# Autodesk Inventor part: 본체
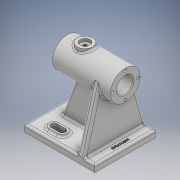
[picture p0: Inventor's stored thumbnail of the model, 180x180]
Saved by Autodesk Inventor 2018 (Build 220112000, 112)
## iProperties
Created: 2019-10
Part Number: 본체
Material: Generic
Document SubType Name: Sheet Metal
Designer: Administrator
Density: 1 g/cm^3
Appearance: Default
Sheet Metal Rule: 기본값
Author: Administrator
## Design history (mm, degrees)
sketch "스케치6"
  geometry: L1 (50, -43)-(-50, -43); L2 (-50, -43)-(-50, 43); L3 (-50, 43)-(50, 43); L4 (50, 43)-(50, -43); L5 (50, -43)-(-50, 43); L6 (-50, -43)-(50, 43); 1 further point
  constraints: 12 end point, 2 midpoint, 2 parallel, 1 horizontal, 1 perpendicular
  dimensions: "d2" = 100 distance of L2.end L3.end; "d3" = 86 distance of L3.end L1.start
extrude "돌출1" new body sketch "스케치6" distance "d4" = 10; taper "d5" = 0 deg
sketch "스케치7"
  geometry: L1 (-50, 0)-(50, 0) reference; L2 (-50, 0)-(-50, 10) reference; L3 (50, 10)-(-50, 10) reference; L4 (50, 0)-(50, 10) reference; L5 (-50, 86)-(32, 86); L6 (-50, 107)-(32, 107); L7 (32, 107)-(32, 86); L8 (-50, 107)-(-50, 86); 1 further point
  constraints: 8 end point, 1 parallel, 1 perpendicular, 1 vertical
  dimensions: "d6" = 86 distance of L1.start L5.start; "d7" = 82 distance of L5.start L5.end; "d8" = 21 distance between parallel lines of L5 L6
revolve "회전1" sketch "스케치7" stored, may be unused: angle "d9" = 90 deg
sketch "스케치8"
  geometry: L1 (50, 0)-(-50, 0) reference; L2 (50, 0)-(50, 10) reference; L3 (-50, 10)-(50, 10) reference; L4 (-50, 0)-(-50, 10) reference; L5 (-50, 65)-(-50, 107) reference; L6 (32, 65)-(32, 107) reference; L7 (-50, 65)-(32, 65) reference; L8 (50, 0)-(50, 10) reference; L9 (-50, 10)-(50, 10) reference; L10 (35, 10)-(13.162, 70); L11 (-25, 70)-(13.162, 70); L12 (35, 10)-(-25, 10); L13 (-25, 10)-(-25, 70); L14 (35, 10)-(-25, 10); 1 further point
  constraints: 10 end point, 2 point on line, 1 collinear, 1 perpendicular
  dimensions: "d12" = 70 deg angle of L3 L10
extrude "돌출2" join sketch "스케치8" stored distance "d14" = 10; taper "d15" = 0 deg
sketch "스케치9"
  geometry: L1 (76, 5)-(20.396, 5) reference; L2 (76, -5)-(76, 5) reference; L3 (20.396, -5)-(76, -5) reference; L4 (76, -43)-(-5.642, -20.228); L5 (76, 43)-(-5.642, 20.228); L6 (76, 43)-(76, -43) reference; L7 (76, -43)-(76, 43); A1 r 21 centre (0, 0) between (20.396, -5) and (20.396, 5) reference; A2 r 21 centre (0, 0) between (20.396, -5) and (20.396, 5) reference; A3 r 21 centre (0, 0) between (-5.642, -20.228) and (-5.642, 20.228); 2 further points
  constraints: 6 end point, 2 point on circle, 1 centre point, 1 coincident, 1 collinear, 1 concentric, 3 other
extrude "돌출3" join sketch "스케치9" distance "d16" = 10; taper "d17" = 0 deg
sketch "스케치10"
  geometry: L1 (-50, 65)-(32, 65) reference; L2 (-50, 107)-(32, 107) reference; L3 (32, 65)-(32, 107) reference; L4 (32, 86)-(32, 100.5); L5 (32, 100.5)-(-30, 100.5); L6 (-30, 100.5)-(-30, 97.5); L7 (-30, 97.5)-(-50, 97.5); L8 (-50, 97.5)-(-50, 86); L9 (-50, 65)-(-50, 107) reference; L10 (32, 86)-(-50, 86); 1 further point
  constraints: 12 end point, 2 vertical, 1 collinear, 1 horizontal
revolve "회전2" sketch "스케치10" stored, may be unused: angle "d21" = 90 deg
sketch "스케치11"
  geometry: C1 r 14.5 at (0, 0) reference; C2 r 21 at (0, 0) reference; 2 further points
hole "구멍1" sketch "스케치11" at (-18, 0) diameter "d23" = 2.459; stored, may be unused: countersink angle "d27" = 90 deg, drill point angle "d29" = 118 deg; dims "d24" = 6, "d25" = 4, "d26" = 8, "d28" = 10
node "작업 평면1"
sketch "스케치14"
  geometry: L1 (-24, 27)-(-12, 27); L2 (-24, 20)-(-12, 20); L3 (-12, 34)-(-24, 34); L4 (-24, -27)-(-12, -27); L5 (-24, -20)-(-12, -20); L6 (-12, -34)-(-24, -34); A1 r 7 centre (-24, 27) between (-24, 34) and (-24, 20); A2 r 7 centre (-12, 27) between (-12, 20) and (-12, 34); A3 r 7 centre (-24, -27) between (-24, -20) and (-24, -34); A4 r 7 centre (-12, -27) between (-12, -34) and (-12, -20); 3 further points
  constraints: 16 end point, 8 point on circle, 4 centre point, 4 tangent, 1 midpoint, 1 parallel
  dimensions: "d44" = 12 distance of L1.start L1.end; "d45" = 14 diameter of A2
extrude "돌출5" join sketch "스케치14" distance "d46" = 3; taper "d47" = 0 deg
sketch "스케치15"
  geometry: 1 further point
sketch "스케치16"
  geometry: L1 (50, -43)-(-50, -43) reference; L2 (-50, -43)-(-50, 43) reference; L3 (-50, 43)-(50, 43) reference; L4 (50, 43)-(50, -43) reference; L5 (-24, 34)-(-12, 34) reference; L6 (-12, 20)-(-24, 20) reference; L7 (-12, -34)-(-24, -34) reference; L8 (-24, -20)-(-12, -20) reference; L9 (25, 43)-(-50, 43) reference; L10 (-50, 43)-(-50, -43) reference; L11 (-50, -43)-(25, -43) reference; L12 (25, -5)-(-35, -5) reference; L13 (-35, -5)-(-35, 5) reference; L14 (-35, 5)-(25, 5) reference; L15 (-24, 27)-(-12, 27); L16 (-24, 22.5)-(-12, 22.5); L17 (-12, 31.5)-(-24, 31.5); L18 (-50, 43)-(-50, -43) reference; L19 (35, 43)-(35, -43) reference; L20 (-24, -27)-(-12, -27); L21 (-24, -31.5)-(-12, -31.5); L22 (-12, -22.5)-(-24, -22.5); L23 (50, -43)-(50, 43) reference; L24 (35, 43)-(35, -43) reference; L25 (35, -43)-(50, -43) reference; L26 (50, 43)-(35, 43) reference; L27 (25, 5)-(25, 43) reference; L28 (25, -43)-(25, -5) reference; A1 r 7 centre (-24, 27) between (-24, 34) and (-24, 20) reference; A2 r 7 centre (-12, 27) between (-12, 20) and (-12, 34) reference; A3 r 7 centre (-12, -27) between (-12, -34) and (-12, -20) reference; A4 r 7 centre (-24, -27) between (-24, -20) and (-24, -34) reference; A5 r 4.5 centre (-24, 27) between (-24, 31.5) and (-24, 22.5); A6 r 4.5 centre (-12, 27) between (-12, 22.5) and (-12, 31.5); A7 r 4.5 centre (-24, -27) between (-24, -22.5) and (-24, -31.5); A8 r 4.5 centre (-12, -27) between (-12, -31.5) and (-12, -22.5); 3 further points
  constraints: 16 end point, 8 point on circle, 8 tangent, 4 centre point, 2 midpoint, 2 parallel
  dimensions: "d48" = 9 diameter of A6; "d49" = 9 diameter of A8
extrude "돌출6" cut sketch "스케치16" distance "d50" = 13; taper "d51" = 0 deg
node "작업 평면2"
sketch "스케치17"
  geometry: L1 (25, 5)-(-14.762, 5) reference; L2 (-14.762, -5)-(25, -5) reference; L3 (50, 21)-(50, -21) reference; L4 (-32, 21)-(-32, -21) reference; L5 (25, 20.228)-(25, 5) reference; L6 (25, -5)-(25, -20.228) reference; L7 (35, -20.228)-(25, -20.228) reference; L8 (35, -20.228)-(35, 20.228) reference; L9 (35, 20.228)-(25, 20.228) reference; C1 r 11 at (-7, 0); 2 further points; 1 other entity
  constraints: 1 centre point, 1 other
  dimensions: "d54" = 22 diameter of C1
extrude "돌출7" join sketch "스케치17" distance "d55" = 8; taper "d56" = 0 deg
sketch "스케치18"
  geometry: C1 r 7 at (0, 0); 2 further points
  constraints: 1 centre point, 1 other
  dimensions: "d57" = 14 diameter of C1
extrude "돌출8" cut sketch "스케치18" distance "d58" = 4; taper "d59" = 0 deg
sketch "스케치19"
  geometry: 2 further points
hole "구멍2" sketch "스케치19" at (0, 0) diameter "d60" = 4.917; stored, may be unused: countersink angle "d64" = 90 deg, drill point angle "d66" = 118 deg; dims "d61" = 12, "d62" = 4, "d63" = 8, "d65" = 17.1
chamfer "모따기1" distance "d67" = 1; stored, may be unused: second distance "d68" = 2, angle "d69" = 45 deg
chamfer "모따기2" distance "d70" = 1; stored, may be unused: second distance "d71" = 2, angle "d72" = 45 deg
fillet "모깎기2" dims "d74" = 3
sketch "스케치25"
  geometry: 1 further point
sketch "스케치26"
  geometry: L1 (-12, 31.5)-(-24, 31.5) reference; L2 (-24, 22.5)-(-12, 22.5) reference; L3 (-12, -22.5)-(-24, -22.5) reference; L4 (-24, -31.5)-(-12, -31.5) reference; L5 (50, -43)-(-50, -43) reference; L6 (-50, -43)-(-50, 43) reference; L7 (-50, 43)-(50, 43) reference; L8 (50, 43)-(50, -43) reference; L9 (50, 43)-(50, -43) reference; L10 (50, -43)-(50, 43); A1 r 4.5 centre (-12, 27) between (-12, 22.5) and (-12, 31.5) reference; A2 r 4.5 centre (-24, 27) between (-24, 31.5) and (-24, 22.5) reference; A3 r 4.5 centre (-12, -27) between (-12, -31.5) and (-12, -22.5) reference; A4 r 4.5 centre (-24, -27) between (-24, -22.5) and (-24, -31.5) reference; 3 further points
  constraints: 2 end point, 1 coincident, 1 vertical, 1 other
extrude "돌출9" join sketch "스케치26" distance "d79" = 0.5; taper "d80" = 0 deg
node "솔리드1"
pattern_circular "원형 패턴1" dims angle "d31" = 360 deg
mirror "미러1"
node "투영된 루프1"
node "투영된 루프2"
node "투영된 루프3"
node "투영된 루프4"
node "투영된 루프5"
node "투영된 루프6"
node "투영된 루프9"
node "투영된 루프10"
node "투영된 루프11"
node "투영된 루프13"
other parameters: "d33" = -41, "K계수" = 4.4, "BendRadius" = 0.5 (derived), "BendReliefWidth" = 0.5 (derived), "BendReliefDepth" = 0.25 (derived), "CornerReliefSize" = 2 (derived), "SeamGap" = 0.01, "MinimumRemnant" = 1 (derived), "TransitionRadius" = 0.5 (= BendRadius)
